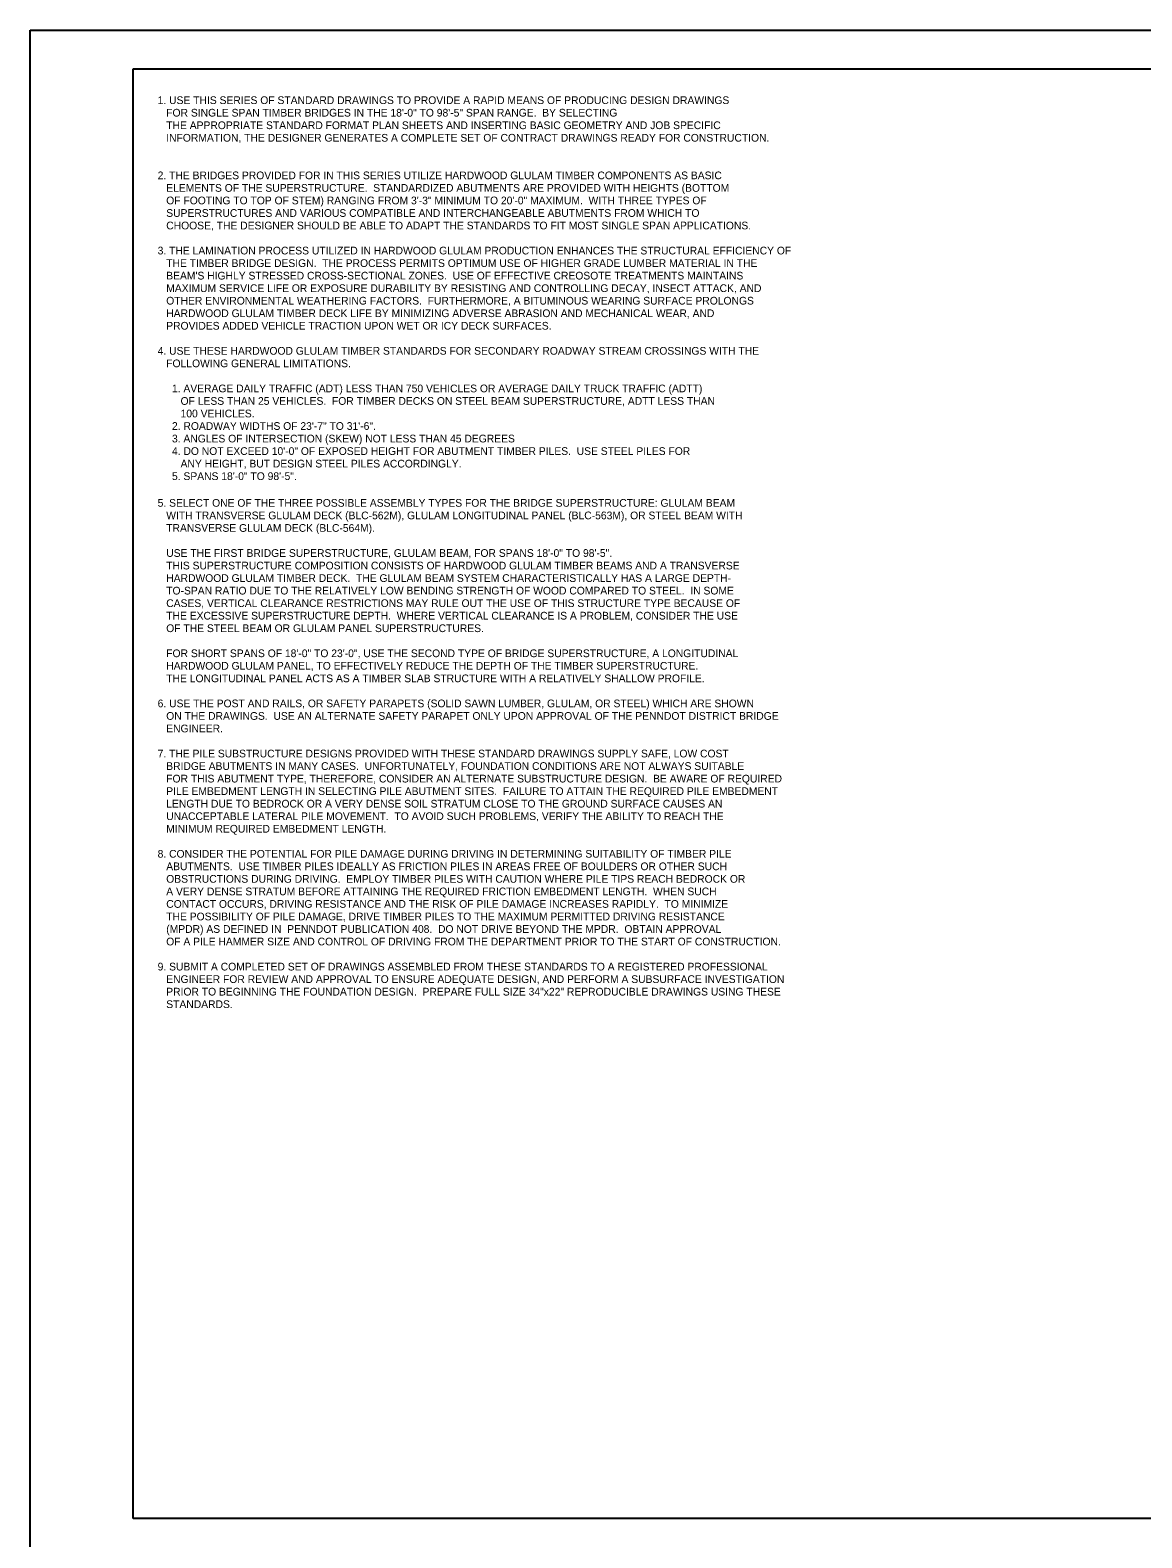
# Model space of a CAD drawing. Extents: x 637594 to 640253, y 297247 to 298435.
# Drawn here: x 639276 to 639709, y 297849 to 298435 of the extents above; entities that cross this region are included whole.
import ezdxf

# ---------------------------------------------------------------- set-up
doc = ezdxf.new("R2010")
doc.units = 0
doc.layers.add('2', color=7, linetype='Continuous')
doc.layers.add('PLT-BNDY', color=7, linetype='Continuous')

msp = doc.modelspace()

# ---------------------------------------------------------------- linework, layer by layer
at = {"layer": '2'}
for p, q in [((639316.46, 297856.46), (639316.46, 298420.46)), ((639316.46, 298420.46), (640102.46, 298420.46)), ((640102.46, 297856.46), (639316.46, 297856.46))]:
    msp.add_line(p, q, dxfattribs=at)
at = {"layer": 'PLT-BNDY'}
msp.add_lwpolyline([(639276.46, 298435.46), (640117.46, 298435.46), (640117.46, 297841.46), (639276.46, 297841.46)], close=True, dxfattribs=at)

# ---------------------------------------------------------------- texts
at = {"layer": '2'}
for s, height, p in [('1. USE THIS SERIES OF STANDARD DRAWINGS TO PROVIDE A RAPID MEANS OF PRODUCING DESIGN DRAWINGS', 3.0001, (639326.01, 298406.71)), ('   THE APPROPRIATE STANDARD FORMAT PLAN SHEETS AND INSERTING BASIC GEOMETRY AND JOB SPECIFIC ', 3.0001, (639326.01, 298396.96)), ('   FOR SINGLE SPAN TIMBER BRIDGES IN THE 18\'-0" TO 98\'-5" SPAN RANGE.  BY SELECTING', 3.0001, (639326.01, 298401.84)), ('   INFORMATION, THE DESIGNER GENERATES A COMPLETE SET OF CONTRACT DRAWINGS READY FOR CONSTRUCTION.', 3.0001, (639326.01, 298392.09)), ('2. THE BRIDGES PROVIDED FOR IN THIS SERIES UTILIZE HARDWOOD GLULAM TIMBER COMPONENTS AS BASIC', 3.0001, (639326.01, 298377.46)), ('   OF FOOTING TO TOP OF STEM) RANGING FROM 3\'-3" MINIMUM TO 20\'-0" MAXIMUM.  WITH THREE TYPES OF', 3.0001, (639326.01, 298367.71)), ('   ELEMENTS OF THE SUPERSTRUCTURE.  STANDARDIZED ABUTMENTS ARE PROVIDED WITH HEIGHTS (BOTTOM', 3.0001, (639326.01, 298372.59)), ('   SUPERSTRUCTURES AND VARIOUS COMPATIBLE AND INTERCHANGEABLE ABUTMENTS FROM WHICH TO', 3.0001, (639326.01, 298362.83)), ('   CHOOSE, THE DESIGNER SHOULD BE ABLE TO ADAPT THE STANDARDS TO FIT MOST SINGLE SPAN APPLICATIONS.', 3.0001, (639326.01, 298357.96)), ('3. THE LAMINATION PROCESS UTILIZED IN HARDWOOD GLULAM PRODUCTION ENHANCES THE STRUCTURAL EFFICIENCY OF ', 3.00014, (639326.01, 298348.21)), ('   THE TIMBER BRIDGE DESIGN.  THE PROCESS PERMITS OPTIMUM USE OF HIGHER GRADE LUMBER MATERIAL IN THE ', 3.00014, (639326.01, 298343.33)), ("   BEAM'S HIGHLY STRESSED CROSS-SECTIONAL ZONES.  USE OF EFFECTIVE CREOSOTE TREATMENTS MAINTAINS ", 3.0001, (639326.01, 298338.46)), ('   MAXIMUM SERVICE LIFE OR EXPOSURE DURABILITY BY RESISTING AND CONTROLLING DECAY, INSECT ATTACK, AND ', 3.00014, (639326.01, 298333.58)), ('   OTHER ENVIRONMENTAL WEATHERING FACTORS.  FURTHERMORE, A BITUMINOUS WEARING SURFACE PROLONGS ', 3.0001, (639326.01, 298328.71)), ('   HARDWOOD GLULAM TIMBER DECK LIFE BY MINIMIZING ADVERSE ABRASION AND MECHANICAL WEAR, AND ', 3.0001, (639326.01, 298323.83)), ('   PROVIDES ADDED VEHICLE TRACTION UPON WET OR ICY DECK SURFACES.', 3.0001, (639326.01, 298318.96)), ('4. USE THESE HARDWOOD GLULAM TIMBER STANDARDS FOR SECONDARY ROADWAY STREAM CROSSINGS WITH THE', 3.0001, (639326.01, 298309.21)), ('   FOLLOWING GENERAL LIMITATIONS.', 3.0001, (639326.01, 298304.33)), ('     1. AVERAGE DAILY TRAFFIC (ADT) LESS THAN 750 VEHICLES OR AVERAGE DAILY TRUCK TRAFFIC (ADTT)', 3.0001, (639326.01, 298294.58)), ('        OF LESS THAN 25 VEHICLES.  FOR TIMBER DECKS ON STEEL BEAM SUPERSTRUCTURE, ADTT LESS THAN', 3.0001, (639326.01, 298289.71)), ('     2. ROADWAY WIDTHS OF 23\'-7" TO 31\'-6".', 3.0001, (639326.01, 298279.96)), ('        100 VEHICLES.', 3.0001, (639326.01, 298284.83)), ('     3. ANGLES OF INTERSECTION (SKEW) NOT LESS THAN 45 DEGREES', 3.0001, (639326.01, 298275.08)), ('     4. DO NOT EXCEED 10\'-0" OF EXPOSED HEIGHT FOR ABUTMENT TIMBER PILES.  USE STEEL PILES FOR', 3.0001, (639326.01, 298270.21)), ('        ANY HEIGHT, BUT DESIGN STEEL PILES ACCORDINGLY.', 3.0001, (639326.01, 298265.33)), ('     5. SPANS 18\'-0" TO 98\'-5".', 3.0001, (639326.01, 298260.45)), ('5. SELECT ONE OF THE THREE POSSIBLE ASSEMBLY TYPES FOR THE BRIDGE SUPERSTRUCTURE: GLULAM BEAM', 3.0001, (639326.01, 298250.06)), ('   WITH TRANSVERSE GLULAM DECK (BLC-562M), GLULAM LONGITUDINAL PANEL (BLC-563M), OR STEEL BEAM WITH ', 3.0001, (639326.01, 298245.18)), ('   TRANSVERSE GLULAM DECK (BLC-564M).', 3.0001, (639326.01, 298240.31)), ('   USE THE FIRST BRIDGE SUPERSTRUCTURE, GLULAM BEAM, FOR SPANS 18\'-0" TO 98\'-5".', 3.0001, (639326.01, 298230.56)), ('   THIS SUPERSTRUCTURE COMPOSITION CONSISTS OF HARDWOOD GLULAM TIMBER BEAMS AND A TRANSVERSE', 3.0001, (639326.01, 298225.68)), ('   HARDWOOD GLULAM TIMBER DECK.  THE GLULAM BEAM SYSTEM CHARACTERISTICALLY HAS A LARGE DEPTH-', 3.0001, (639326.01, 298220.81)), ('   TO-SPAN RATIO DUE TO THE RELATIVELY LOW BENDING STRENGTH OF WOOD COMPARED TO STEEL.  IN SOME', 3.0001, (639326.01, 298215.93)), ('   CASES, VERTICAL CLEARANCE RESTRICTIONS MAY RULE OUT THE USE OF THIS STRUCTURE TYPE BECAUSE OF', 3.0001, (639326.01, 298211.05)), ('   THE EXCESSIVE SUPERSTRUCTURE DEPTH.  WHERE VERTICAL CLEARANCE IS A PROBLEM, CONSIDER THE USE', 3.0001, (639326.01, 298206.18)), ('   OF THE STEEL BEAM OR GLULAM PANEL SUPERSTRUCTURES.', 3.0001, (639326.01, 298201.3)), ('   FOR SHORT SPANS OF 18\'-0" TO 23\'-0", USE THE SECOND TYPE OF BRIDGE SUPERSTRUCTURE, A LONGITUDINAL', 3.0001, (639326.01, 298191.55)), ('   HARDWOOD GLULAM PANEL, TO EFFECTIVELY REDUCE THE DEPTH OF THE TIMBER SUPERSTRUCTURE.', 3.0001, (639326.01, 298186.68)), ('   THE LONGITUDINAL PANEL ACTS AS A TIMBER SLAB STRUCTURE WITH A RELATIVELY SHALLOW PROFILE.', 3.0001, (639326.01, 298181.8)), ('6. USE THE POST AND RAILS, OR SAFETY PARAPETS (SOLID SAWN LUMBER, GLULAM, OR STEEL) WHICH ARE SHOWN ', 3.0001, (639326.01, 298172.05)), ('   ON THE DRAWINGS.  USE AN ALTERNATE SAFETY PARAPET ONLY UPON APPROVAL OF THE PENNDOT DISTRICT BRIDGE ', 3.00014, (639326.01, 298167.18)), ('   ENGINEER.', 3.0001, (639326.01, 298162.3)), ('7. THE PILE SUBSTRUCTURE DESIGNS PROVIDED WITH THESE STANDARD DRAWINGS SUPPLY SAFE, LOW COST', 3.0001, (639326.01, 298152.55)), ('   BRIDGE ABUTMENTS IN MANY CASES.  UNFORTUNATELY, FOUNDATION CONDITIONS ARE NOT ALWAYS SUITABLE', 3.0001, (639326.01, 298147.68)), ('   FOR THIS ABUTMENT TYPE, THEREFORE, CONSIDER AN ALTERNATE SUBSTRUCTURE DESIGN.  BE AWARE OF REQUIRED ', 3.00014, (639326.01, 298142.8)), ('   PILE EMBEDMENT LENGTH IN SELECTING PILE ABUTMENT SITES.  FAILURE TO ATTAIN THE REQUIRED PILE EMBEDMENT', 3.00014, (639326.01, 298137.93)), ('   LENGTH DUE TO BEDROCK OR A VERY DENSE SOIL STRATUM CLOSE TO THE GROUND SURFACE CAUSES AN ', 3.0001, (639326.01, 298133.05)), ('   UNACCEPTABLE LATERAL PILE MOVEMENT.  TO AVOID SUCH PROBLEMS, VERIFY THE ABILITY TO REACH THE', 3.0001, (639326.01, 298128.18)), ('   MINIMUM REQUIRED EMBEDMENT LENGTH.', 3.0001, (639326.01, 298123.3)), ('8. CONSIDER THE POTENTIAL FOR PILE DAMAGE DURING DRIVING IN DETERMINING SUITABILITY OF TIMBER PILE ', 3.0001, (639326.01, 298113.55)), ('   ABUTMENTS.  USE TIMBER PILES IDEALLY AS FRICTION PILES IN AREAS FREE OF BOULDERS OR OTHER SUCH', 3.0001, (639326.01, 298108.68)), ('   OBSTRUCTIONS DURING DRIVING.  EMPLOY TIMBER PILES WITH CAUTION WHERE PILE TIPS REACH BEDROCK OR', 3.0001, (639326.01, 298103.8)), ('   A VERY DENSE STRATUM BEFORE ATTAINING THE REQUIRED FRICTION EMBEDMENT LENGTH.  WHEN SUCH  ', 3.0001, (639326.01, 298098.92)), ('   CONTACT OCCURS, DRIVING RESISTANCE AND THE RISK OF PILE DAMAGE INCREASES RAPIDLY.  TO MINIMIZE', 3.0001, (639326.01, 298094.05)), ('   THE POSSIBILITY OF PILE DAMAGE, DRIVE TIMBER PILES TO THE MAXIMUM PERMITTED DRIVING RESISTANCE', 3.0001, (639326.01, 298089.17)), ('   (MPDR) AS DEFINED IN  PENNDOT PUBLICATION 408.  DO NOT DRIVE BEYOND THE MPDR.  OBTAIN APPROVAL', 3.0001, (639326.01, 298084.3)), ('   OF A PILE HAMMER SIZE AND CONTROL OF DRIVING FROM THE DEPARTMENT PRIOR TO THE START OF CONSTRUCTION.', 3.00014, (639326.01, 298079.42)), ('9. SUBMIT A COMPLETED SET OF DRAWINGS ASSEMBLED FROM THESE STANDARDS TO A REGISTERED PROFESSIONAL ', 3.0001, (639326.01, 298069.67)), ('   ENGINEER FOR REVIEW AND APPROVAL TO ENSURE ADEQUATE DESIGN, AND PERFORM A SUBSURFACE INVESTIGATION', 3.00014, (639326.01, 298064.8)), ('   PRIOR TO BEGINNING THE FOUNDATION DESIGN.  PREPARE FULL SIZE 34"x22" REPRODUCIBLE DRAWINGS USING THESE', 3.00014, (639326.01, 298059.92)), ('   STANDARDS.', 3.0001, (639326.01, 298055.05))]:
    msp.add_text(s, height=height, dxfattribs=at).set_placement(p)

doc.saveas('drawing.dxf')
